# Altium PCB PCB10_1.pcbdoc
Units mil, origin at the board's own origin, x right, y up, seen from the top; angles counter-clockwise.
Board outline 2455 x 1010 mil, 6 copper layers (Top Layer, GND, Inner2, Inner3, 3.3, Bottom Layer); 64 components, 81 nets, 315 pads, 60 vias.
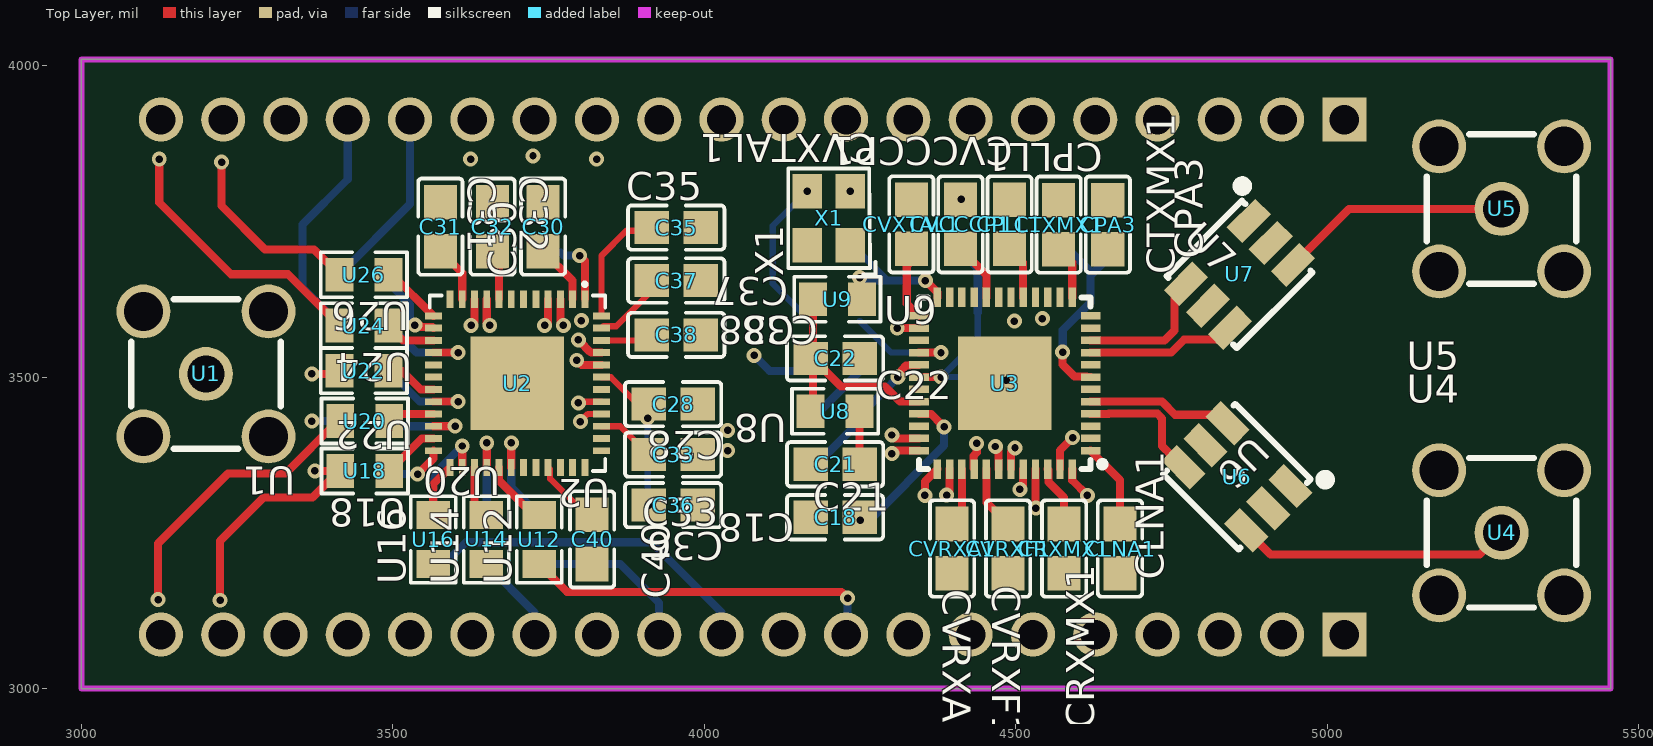
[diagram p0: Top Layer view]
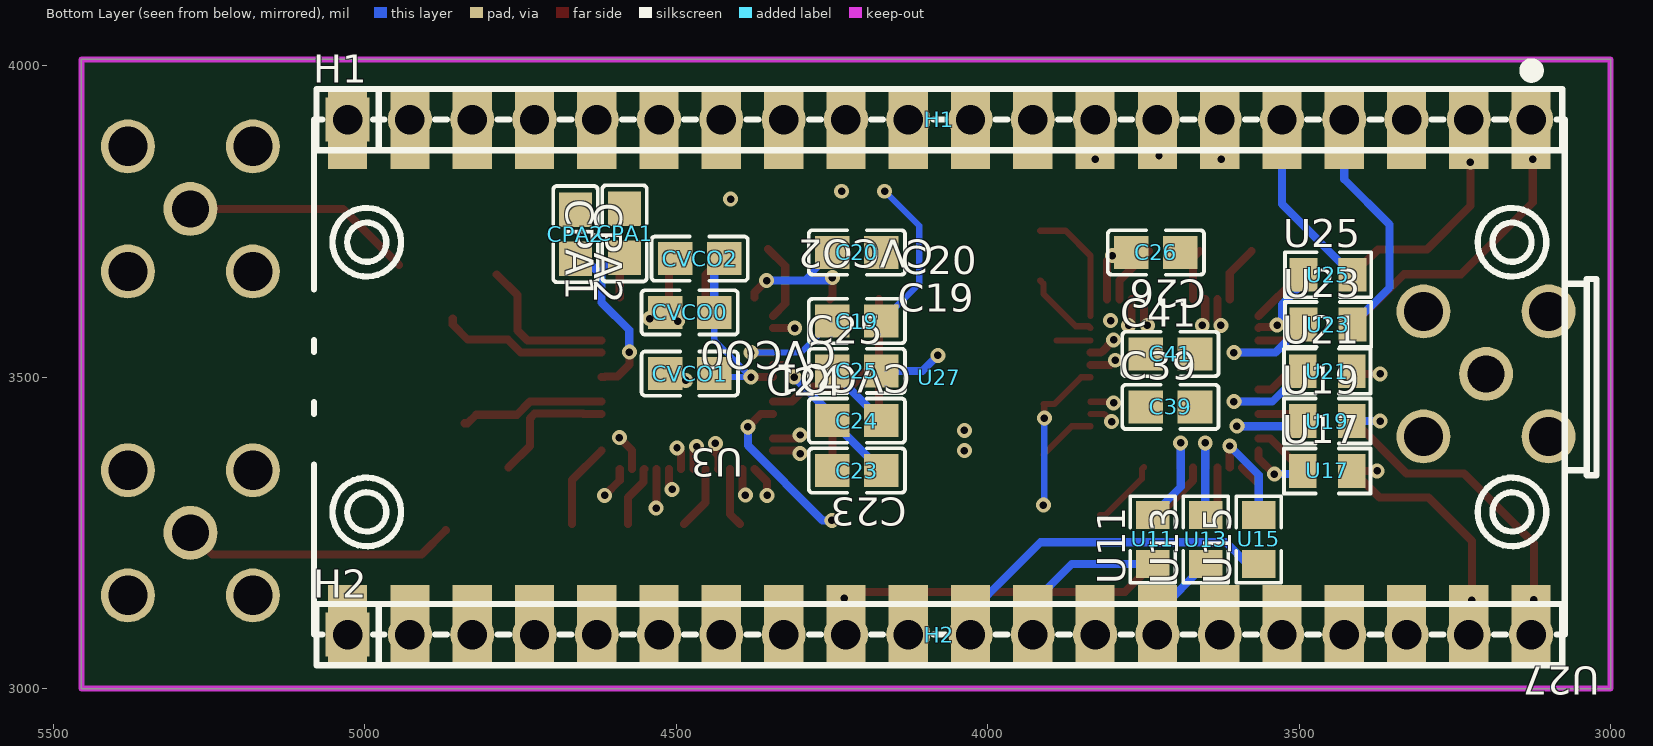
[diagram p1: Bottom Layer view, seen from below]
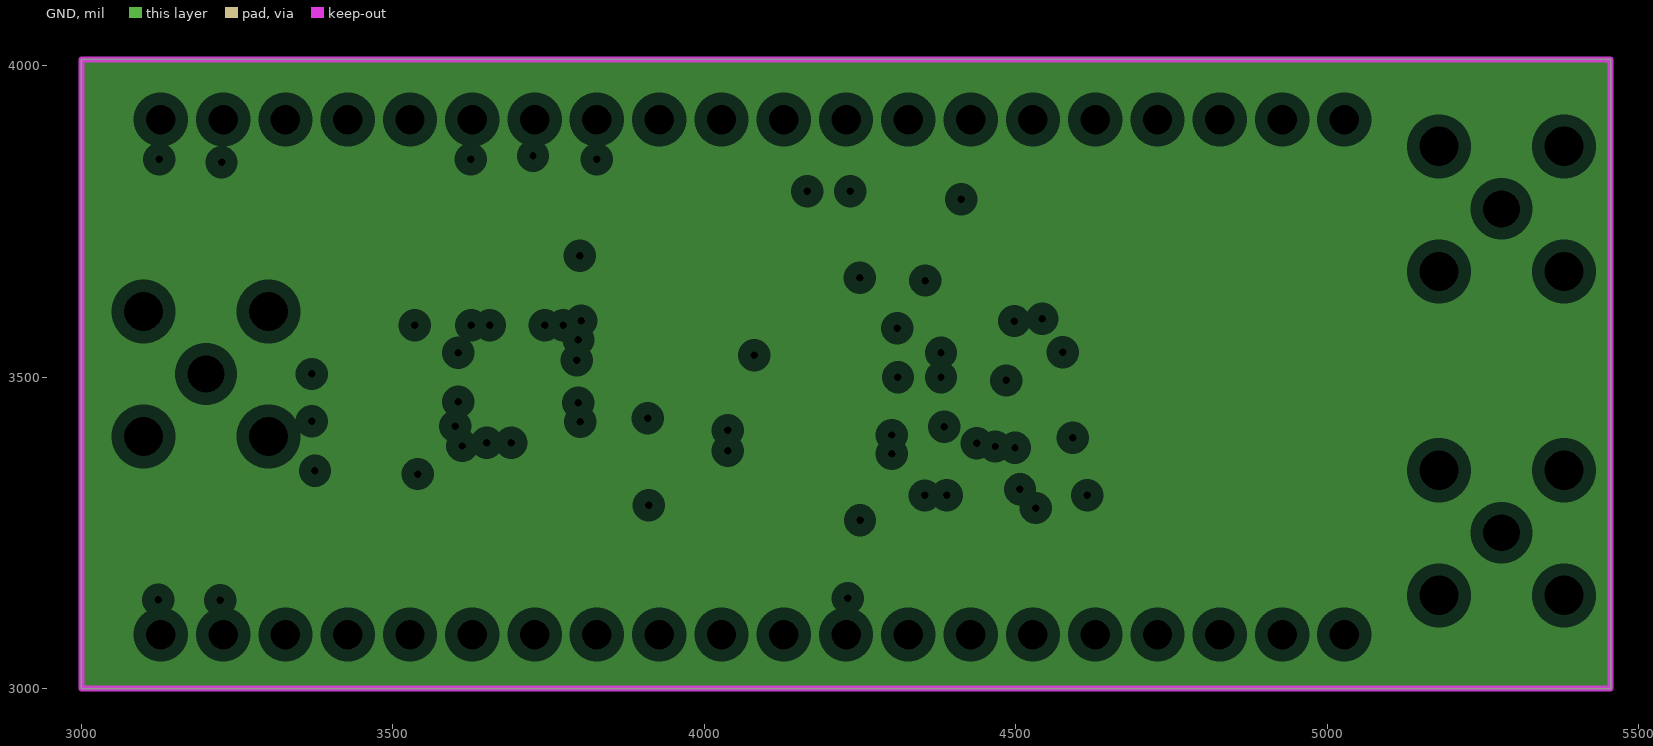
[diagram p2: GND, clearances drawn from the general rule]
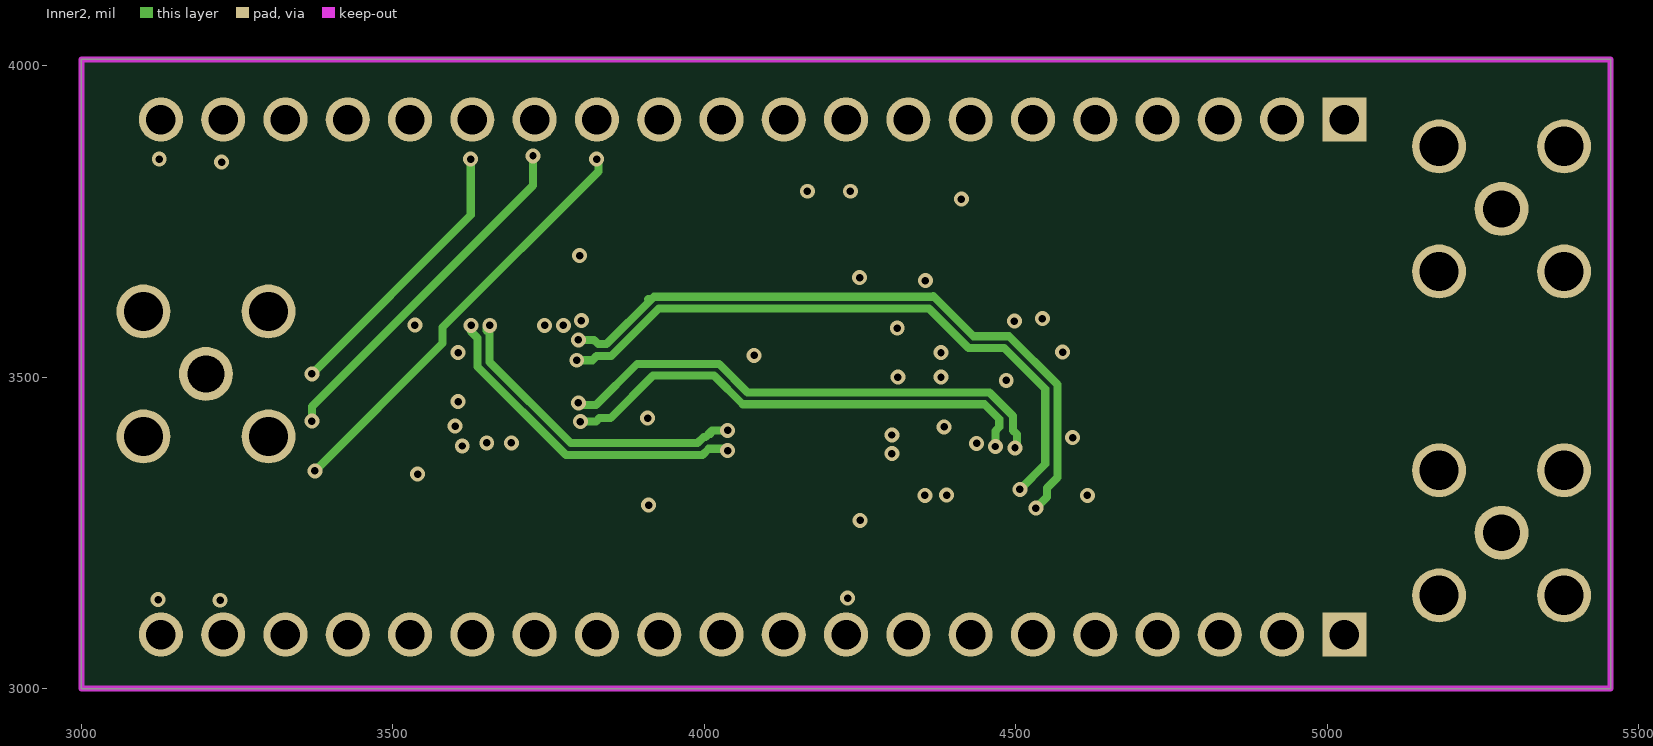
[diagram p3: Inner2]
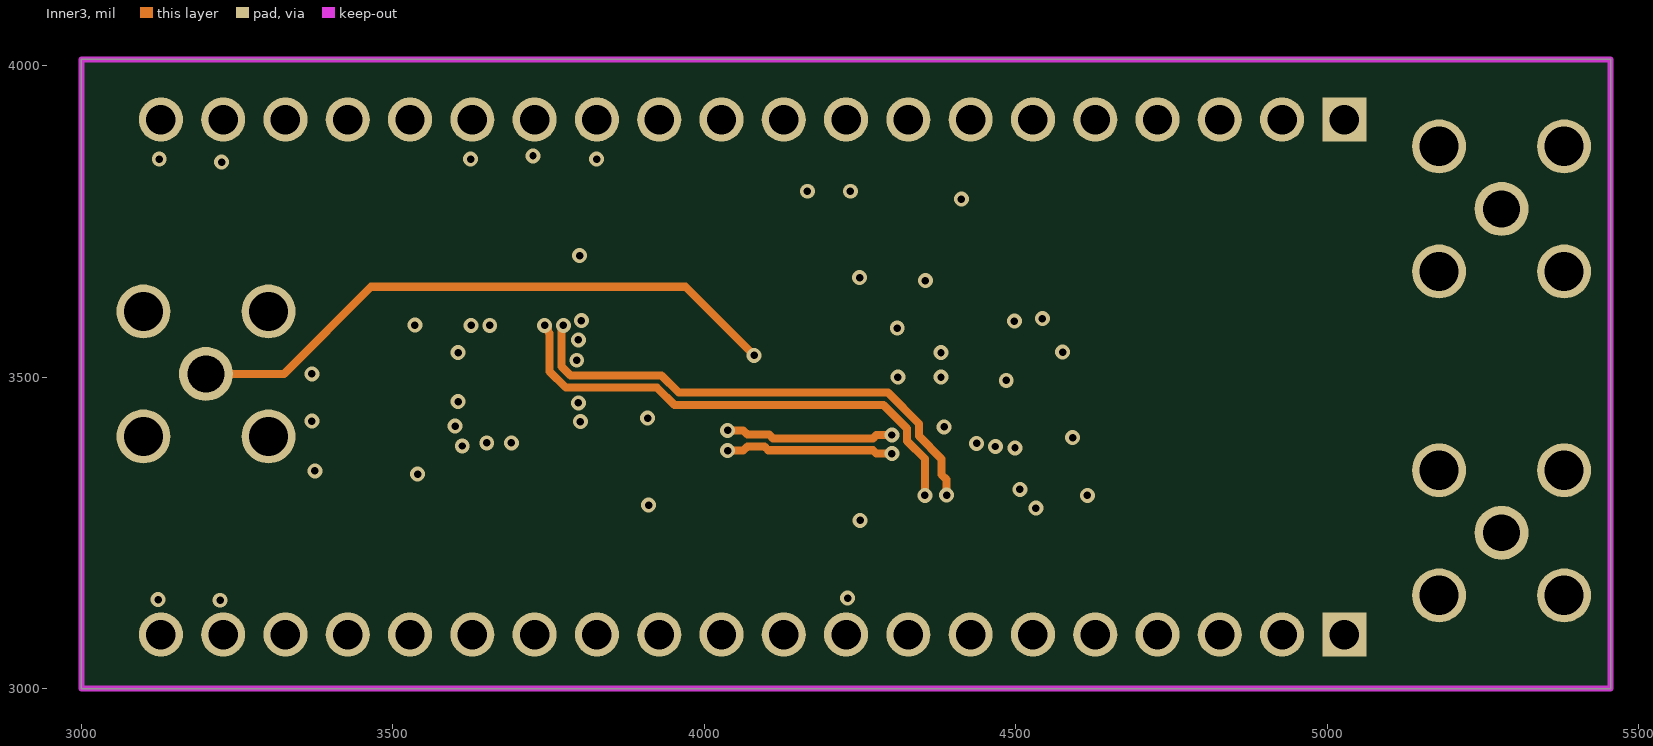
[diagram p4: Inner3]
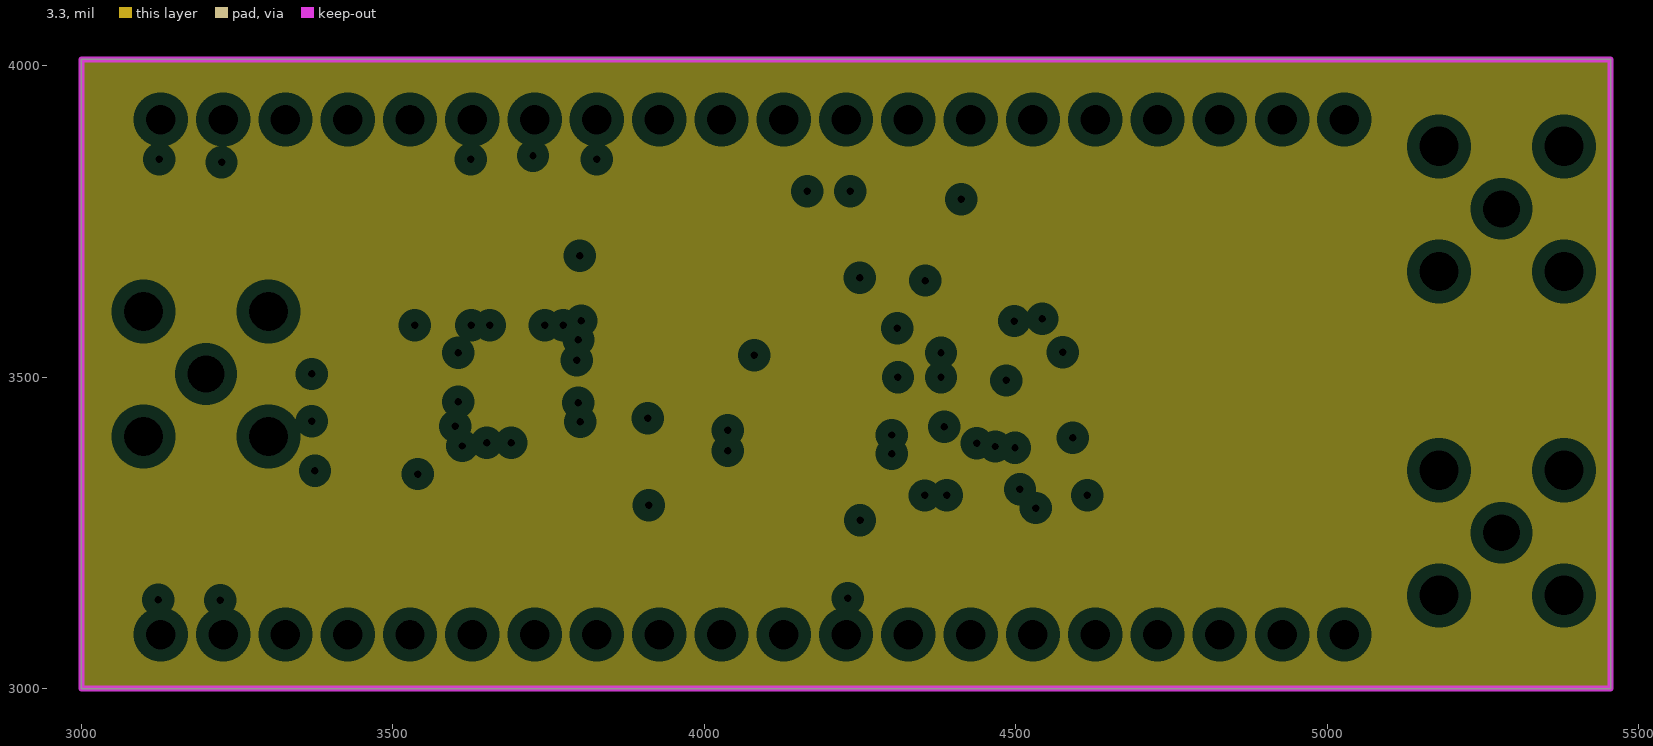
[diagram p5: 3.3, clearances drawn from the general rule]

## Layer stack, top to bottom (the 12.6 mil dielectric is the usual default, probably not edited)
Top Layer: signal copper (thickness not stored)
Dielectric: dielectric 12.6, FR-4, Dk 4.8
GND: plane copper (thickness not stored)
Dielectric: dielectric 12.6, FR-4, Dk 4.8
Inner2: signal copper (thickness not stored)
Dielectric: dielectric 12.6, FR-4, Dk 4.8
Inner3: signal copper (thickness not stored)
Dielectric: dielectric 12.6, FR-4, Dk 4.8
3.3: plane copper (thickness not stored)
Dielectric: dielectric 12.6, FR-4, Dk 4.8
Bottom Layer: signal copper (thickness not stored)

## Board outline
3000,4010 5455,4010 5455,3000 3000,3000

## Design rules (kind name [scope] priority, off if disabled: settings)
BoardOutlineClearance copperThickness1oz [All] p0: genericclearance=10 ignorepadtopadclearanceinfootprint=FALSE except(0: Arc-SplitContinuation Track-SplitContinuation SMDPad-SplitContinuation THPad-SplitContinuation Via-SplitContinuation Fill-SplitContinuation Poly-SplitContinuation Region-SplitContinuation Text-SplitContinuation; 6: Track-CutoutEdge SMDPad-CutoutEdge THPad-CutoutEdge Via-CutoutEdge Region-CutoutEdge; 11.8: Track-OutlineEdge SMDPad-OutlineEdge THPad-OutlineEdge Via-OutlineEdge Fill-OutlineEdge Region-OutlineEdge Poly-OutlineEdge Text-OutlineEdge Fill-CutoutEdge)
BoardOutlineClearance copperThickness2oz [All] p0: genericclearance=10 ignorepadtopadclearanceinfootprint=FALSE except(0: Arc-SplitContinuation Track-SplitContinuation SMDPad-SplitContinuation THPad-SplitContinuation Via-SplitContinuation Fill-SplitContinuation Poly-SplitContinuation Region-SplitContinuation Text-SplitContinuation; 6: Track-CutoutEdge SMDPad-CutoutEdge THPad-CutoutEdge Via-CutoutEdge Region-CutoutEdge; 11.8: Track-OutlineEdge SMDPad-OutlineEdge THPad-OutlineEdge Via-OutlineEdge Fill-OutlineEdge Region-OutlineEdge Poly-OutlineEdge Text-OutlineEdge Fill-CutoutEdge)
Clearance copperThickness1oz [(InNet('$1I297\BYPASS') OR InNet('GND') OR InNet('$1I297\XTAL') OR InNet('$1I297\$1N2490') OR InNet('$1I297\CPOUT') OR InNet('$1I297\$1N1515') OR InNet('$1I297\TUNE') OR InNet('$1I297\$1N2254') OR InNet('3.3') OR InNet('$1I297\D6') OR InNet('$1I297\RXP') OR InNet('$1I297\RXN') OR InNet('$1I297\D7') OR InNet('$1I297\D3') OR InNet('$1I297\TXP') OR InNet('$1I297\TXN') OR InNet('$1I297\D2') OR InNet('$1I297\SHDN#') OR InNet('$1I297\D4') OR InNet('$1I297\D5') OR InNet('$1I297\CS#') OR InNet('$1I297\RSSI') OR InNet('$1I297\SCLK') OR InNet('$1I297\DIN') OR InNet('$1I297\CLKBUF') OR InNet('$1I297\PLL_LOCK') OR InNet('$1I297\D1') OR InNet('$1I297\RXHP') OR InNet('$1I297\RXTX_MODE') OR InNet('$1I297\$1N1513') OR InNet('$1I297\$1N1514') OR InNet('$1I61\$1N1654') OR InNet('$1I61\$1N1653') OR InNet('$1I61\$1N1602') OR InNet('$1I61\BBC_CLK') OR InNet('$1I61\$1N1651') OR InNet('$1I61\$1N1648') OR InNet('$1I61\$1N1645') OR InNet('$1I61\$1N1642') OR InNet('$1I61\$1N1639') OR InNet('$1I61\$1N1636') OR InNet('$1I61\$1N1633') OR InNet('$1I61\$1N1662') OR InNet('$1I61\$1N1628') OR InNet('$1I61\$1N1625') OR InNet('$1I61\$1N1620') OR InNet('$1I61\$1N1617') OR InNet('$1I61\$1N1614') OR InNet('$1I61\$1N1611') OR InNet('$1I61\$1N1608') OR InNet('$1I61\$1N1605') OR InNet('$1I61\DIN') OR InNet('$1I61\SCLK') OR InNet('$1I61\CS#') OR InNet('$1I61\BBC_DD7') OR InNet('$1I61\BBC_DD6') OR InNet('$1I61\BBC_DD5') OR InNet('$1I61\BBC_DD4') OR InNet('$1I61\BBC_DD3') OR InNet('$1I61\BBC_DD2') OR InNet('$1I61\BBC_DD1') OR InNet('$1I61\BBC_DD0') OR InNet('$1I61\BBC_DA7') OR InNet('$1I61\BBC_DA6') OR InNet('$1I61\BBC_DA5') OR InNet('$1I61\BBC_DA4') OR InNet('$1I61\BBC_DA3') OR InNet('$1I61\BBC_DA2') OR InNet('$1I61\BBC_DA1') OR InNet('$1I61\BBC_DA0') OR InNet('RXQN') OR InNet('RXQP') OR InNet('RXIN') OR InNet('RXIP') OR InNet('TXQN') OR InNet('TXQP') OR InNet('TXIN') OR InNet('TXIP') OR InNet('+5V') OR InNet('VCC') OR InNet('$1I297\$1N3884'))] p1: gap=7 ignorepadtopadclearanceinfootprint=FALSE except(4: Track-Track; 6: Track-SMDPad SMDPad-SMDPad Track-THPad SMDPad-THPad THPad-THPad Track-Via SMDPad-Via THPad-Via Via-Via SMDPad-Fill THPad-Fill Via-Fill Fill-Fill Track-Region SMDPad-Region THPad-Region Via-Region Region-Region Track-Poly SMDPad-Poly THPad-Poly Via-Poly Fill-Poly Region-Poly Poly-Poly Track-Text SMDPad-Text THPad-Text Via-Text Fill-Text Region-Text Poly-Text Text-Text; 6.9: Track-Hole SMDPad-Hole THPad-Hole Via-Hole Fill-Hole Region-Hole Poly-Hole Text-Hole Sheet-Hole; 11.8: Track-Fill Fill-Region Track-Sheet SMDPad-Sheet THPad-Sheet Via-Sheet Fill-Sheet Region-Sheet Poly-Sheet Text-Sheet)
Clearance copperThickness2oz [All] p1: gap=7 ignorepadtopadclearanceinfootprint=FALSE except(6: Track-SMDPad SMDPad-SMDPad Track-THPad SMDPad-THPad THPad-THPad Track-Via SMDPad-Via THPad-Via Via-Via SMDPad-Fill THPad-Fill Via-Fill Fill-Fill Track-Region SMDPad-Region THPad-Region Via-Region Region-Region Track-Poly SMDPad-Poly THPad-Poly Via-Poly Fill-Poly Region-Poly Poly-Poly Track-Text SMDPad-Text THPad-Text Via-Text Fill-Text Region-Text Poly-Text Text-Text; 6.9: Track-Hole SMDPad-Hole THPad-Hole Via-Hole Fill-Hole Region-Hole Poly-Hole Text-Hole Sheet-Hole; 8: Track-Track; 11.8: Track-Fill Fill-Region Track-Sheet SMDPad-Sheet THPad-Sheet Via-Sheet Fill-Sheet Region-Sheet Poly-Sheet Text-Sheet)
DiffPairsRouting differentialPair [All] p1: maxuncoupledlength=10 minlimit=6 maxlimit=6 mostfreqgap=6 toplayer_minwidth=5 toplayer_prefwidth=10 toplayer_maxwidth=100 bottomlayer_minwidth=5 bottomlayer_prefwidth=10 bottomlayer_maxwidth=100 midlayer2_minwidth=5 midlayer2_prefwidth=10 midlayer2_maxwidth=100 midlayer3_minwidth=5 midlayer3_prefwidth=10 midlayer3_maxwidth=100
PasteMaskExpansion pasteMaskExpansion [All] p1: expansion=0
PlaneConnect innerPlane [All] p1: planeconnectstyle=Relief reliefexpansion=20 reliefentries=4 reliefconductorwidth=10 reliefairgap=10
PolygonConnect copperRegion [All] p1: connectstyle=Relief reliefentries=4 reliefconductorwidth=10 polygonreliefangle="90 Angle" airgapwidth=10
RoutingVias viaSize [All] p1: viastyle="Through Hole" holewidth=12.0078 minholewidth=11.811 maxholewidth=248.0314 width=24.0158 minwidth=19.685 maxwidth=393.7008
SolderMaskExpansion solderMaskExpansion [All] p1: useseparateexpansions=TRUE expansion=2 expansionbottom=2
Width copperThickness1oz [All] p1: maxlimit=100 minlimit=5 preferedwidth=10
Width copperThickness2oz [All] p1: maxlimit=100 minlimit=8 preferedwidth=10

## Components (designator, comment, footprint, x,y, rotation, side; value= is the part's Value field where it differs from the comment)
C18 "CAP_0603" C0805 4210,3275 r0 top
C19 "CAP_0603" C0805 4210,3590 r0 bottom
C20 "CAP_0603" C0805 4210,3700 r0 bottom
C21 "CAP_0603" C0805 4210,3360 r0 top
C22 "CAP_0603" C0805 4210,3530 r180 top
C23 "CAP_0603" C0805 4210,3350 r0 bottom
C24 "CAP_0805" C0805 4210,3430 r180 bottom
C25 "CAP_0805" C0805 4210,3510 r180 bottom
C26 "CAP_0805" C0805 3730,3700 r0 bottom
C28 "CAP_0805" C0805 3950,3456.6 r180 top
C30 "CAP_0805" C0805 3741.35,3741.45 r90 top
C31 "CAP_0805" C0805 3576.3,3741.45 r270 top
C32 "CAP_0805" C0805 3659.94,3741.45 r270 top
C33 "CAP_0805" C0805 3950,3375.47 r0 top
C35 "CAP_0805" C0805 3955,3740 r0 top
C36 "CAP_0805" C0805 3950,3294.34 r180 top
C37 "CAP_0805" C0805 3955,3655 r180 top
C38 "CAP_0805" C0805 3955,3567.73 r180 top
C39 "CAP_0805" C0805 3706.63,3452.1 r180 bottom
C40 "CAP_0805" C0805 3819.94,3239.34 r90 top
C41 "CAP_0805" C0805 3706.63,3537.1 r180 bottom
CLNA1 "CAP_0603" C0805 4667.43,3224.74 r270 top
CPA1 "CAP_0603" C0805 4583.06,3730.72 r90 bottom
CPA2 "CAP_0603" C0805 4661.8,3729.46 r90 bottom
CPA3 "CAP_0603" C0805 4647.79,3744.74 r90 top
CPLL1 "CAP_0603" C0805 4490.11,3745.09 r90 top
CRXMX1 "CAP_0603" C0805 4577.55,3224.74 r270 top
CTXMX1 "CAP_0603" C0805 4568.95,3744.74 r90 top
CVCCCP1 "CAP_0603" C0805 4411.27,3745.09 r90 top
CVCO0 "CAP_0603" C0805 4478.42,3603.74 r0 bottom
CVCO1 "CAP_0603" C0805 4478.37,3505.55 r0 bottom
CVCO2 "CAP_0603" C0805 4462.43,3690.09 r0 bottom
CVRXA1 "CAP_0603" C0805 4397.79,3224.74 r270 top
CVRXF1 "CAP_0603" C0805 4487.67,3224.74 r270 top
CVXTAL1 "CAP_0603" C0805 4332.43,3745.09 r90 top
H1 "HDR-M_2.54_1x20P" HDR-TH_20P-P2.54-V-M-1 4077.6,3913.39 r180 bottom
H2 "HDR-M_2.54_1x20P" HDR-TH_20P-P2.54-V-M-1 4077.6,3086.61 r180 bottom
U1 "MCX5.08-H5_C9900009324" SMA-TH_MCX5.08-H5 3200,3505 r180 top
U2 "MAX5864ETM+" QFN-48_L7.0-W7.0-P0.50-BL-EP5.1 3700,3490 r180 top
U3 "MAX2831ETM+T" TQFN-48_L7.0-W7.0-P0.50-TL-EP5.6 4482.43,3490.09 r180 top
U4 "MCX5.08-H5_C9900009324" SMA-TH_MCX5.08-H5 5280,3250 r0 top
U5 "MCX5.08-H5_C9900009324" SMA-TH_MCX5.08-H5 5280,3770 r0 top
U6 "TCM2-43X+" IND-SMD_6P-L4.1-W3.8-P1.27-TL 4855,3340 r225 top
U7 "TCM2-43X+" IND-SMD_6P-L4.1-W3.8-P1.27-TL 4859.01,3665 r315 top
U8 "SCR0805J1M" R0805 4210,3445 r0 top
U9 "SCR0805J1M" R0805 4213.74,3625 r0 top
U11 "3R00" R0805 3734.94,3239.34 r90 bottom
U12 "3R00" R0805 3734.94,3239.34 r90 top
U13 "3R00" R0805 3649.94,3239.34 r90 bottom
U14 "3R00" R0805 3649.94,3239.34 r90 top
U15 "3R00" R0805 3564.94,3239.34 r90 bottom
U16 "3R00" R0805 3564.94,3239.34 r90 top
U17 "3R00" R0805 3454.94,3349.34 r180 bottom
U18 "3R00" R0805 3454.94,3349.34 r180 top
U19 "3R00" R0805 3454.94,3429.34 r180 bottom
U20 "3R00" R0805 3454.94,3429.34 r180 top
U21 "3R00" R0805 3454.94,3509.34 r180 bottom
U22 "3R00" R0805 3453.53,3510 r180 top
U23 "3R00" R0805 3453.53,3584.34 r180 bottom
U24 "3R00" R0805 3453.53,3582.61 r180 top
U25 "3R00" R0805 3453.53,3664.34 r180 bottom
U26 "3R00" R0805 3453.53,3664.34 r180 top
U27 "PICO" comm-smd_l51.0-w21.0-p2.54_sc0916 4090,3500 r0 bottom
X1 "SX3M40.000E20F30THN" OSC-SMD_4P-L3.2-W2.5-BL 4200,3755 r90 top

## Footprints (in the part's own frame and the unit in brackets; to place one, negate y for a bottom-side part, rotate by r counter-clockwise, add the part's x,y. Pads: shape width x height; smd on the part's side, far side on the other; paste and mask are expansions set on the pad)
C0805 [mm]
  rect 1.41x1.35 smd: 1(-1,0) 2(1,0)
  silkscreen extent -1.96,-0.9 1.96,0.9
comm-smd_l51.0-w21.0-p2.54_sc0916 [mm]
  rect 1.6x3.2 smd: 1(-24.445,-10.087) 2(-21.905,-10.087) 3(-19.365,-10.087) 4(-16.825,-10.087) 5(-14.285,-10.087) 6(-11.745,-10.087) 7(-9.205,-10.087) 8(-6.665,-10.087) 9(-4.125,-10.087) 10(-1.585,-10.087) 11(0.955,-10.087) 12(3.495,-10.087) 13(6.035,-10.087) 14(8.575,-10.087) 15(11.115,-10.087) 16(13.655,-10.087) 17(16.195,-10.087) 18(18.735,-10.087) 19(21.275,-10.087) 20(23.815,-10.087) 21(23.815,10.087) 22(21.275,10.087) 23(18.735,10.087) 24(16.195,10.087) 25(13.655,10.087) 26(11.115,10.087) 27(8.575,10.087) 28(6.035,10.087) 29(3.495,10.087) 30(0.955,10.087) 31(-1.585,10.087) 32(-4.125,10.087) 33(-6.665,10.087) 34(-9.205,10.087) 35(-11.745,10.087) 36(-14.285,10.087) 37(-16.825,10.087) 38(-19.365,10.087) 39(-21.905,10.087) 40(-24.445,10.087)
  silkscreen extent -27.11,-12.75 25.18,10.5
HDR-TH_20P-P2.54-V-M-1 [mm]
  rect 1.8x1.8 hole 1.2: 1(-24.13,0)
  round 1.8 hole 1.2: 2(-21.59,0) 3(-19.05,0) 4(-16.51,0) 5(-13.97,0) 6(-11.43,0) 7(-8.89,0) 8(-6.35,0) 9(-3.81,0) 10(-1.27,0) 11(1.27,0) 12(3.81,0) 13(6.35,0) 14(8.89,0) 15(11.43,0) 16(13.97,0) 17(16.51,0) 18(19.05,0) 19(21.59,0) 20(24.13,0)
  silkscreen extent -25.4,-1.25 25.4,1.25
IND-SMD_6P-L4.1-W3.8-P1.27-TL [mm]
  rect 0.9x1.657 smd: 1(-1.27,1.814) 2(0,1.814) 3(1.27,1.814) 4(1.27,-1.814) 5(0,-1.814) 6(-1.27,-1.814)
  silkscreen extent -2.66,-2.2 2.05,2.83
OSC-SMD_4P-L3.2-W2.5-BL [mm]
  rect 1.4x1.2 smd: 1(-1.1,-0.875) 2(1.1,-0.875) 3(1.1,0.875) 4(-1.1,0.875)
  silkscreen extent -2.29,-1.9 2.03,1.65
QFN-48_L7.0-W7.0-P0.50-BL-EP5.1 [mm]
  rect 0.28x0.7 smd: 1(-2.75,-3.427) 2(-2.25,-3.427) 3(-1.75,-3.427) 4(-1.25,-3.427) 5(-0.75,-3.427) 6(-0.25,-3.427) 7(0.25,-3.427) 8(0.75,-3.427) 9(1.25,-3.427) 10(1.75,-3.427) 11(2.25,-3.427) 12(2.75,-3.427) 25(2.75,3.427) 26(2.25,3.427) 27(1.75,3.427) 28(1.25,3.427) 29(0.75,3.427) 30(0.25,3.427) 31(-0.25,3.427) 32(-0.75,3.427) 33(-1.25,3.427) 34(-1.75,3.427) 35(-2.25,3.427) 36(-2.75,3.427)
  rect 0.7x0.28 smd: 13(3.427,-2.75) 14(3.427,-2.25) 15(3.427,-1.75) 16(3.427,-1.25) 17(3.427,-0.75) 18(3.427,-0.25) 19(3.427,0.25) 20(3.427,0.75) 21(3.427,1.25) 22(3.427,1.75) 23(3.427,2.25) 24(3.427,2.75) 37(-3.427,2.75) 38(-3.427,2.25) 39(-3.427,1.75) 40(-3.427,1.25) 41(-3.427,0.75) 42(-3.427,0.25) 43(-3.427,-0.25) 44(-3.427,-0.75) 45(-3.427,-1.25) 46(-3.427,-1.75) 47(-3.427,-2.25) 48(-3.427,-2.75)
  rect 3.81x3.81 smd: 49(0,0)
  silkscreen extent -3.58,-4.11 3.58,3.58
R0805 [mm]
  rect 1.133x1.377 smd: 1(-1,0) 2(1,0)
  silkscreen extent -1.76,-0.92 1.76,0.92
SMA-TH_MCX5.08-H5 [mm]
  round 2.2 hole 1.6: 1(-2.55,-2.55) 2(-2.55,2.55) 3(2.55,2.55)
  round 2.2 hole 1.6 copper offset 0,0: 4(2.55,-2.55)
  round 2.2 hole 1.5: 5(0,0)
  silkscreen extent -3.05,-3.05 3.05,3.05
TQFN-48_L7.0-W7.0-P0.50-TL-EP5.6 [mm]
  rect 0.8x0.3 smd: 1(-3.5,2.751) 2(-3.5,2.25) 3(-3.5,1.75) 4(-3.5,1.251) 5(-3.5,0.75) 6(-3.5,0.251) 7(-3.5,-0.249) 8(-3.5,-0.749) 9(-3.5,-1.25) 10(-3.5,-1.75) 11(-3.5,-2.249) 12(-3.5,-2.748) 25(3.5,-2.748) 26(3.5,-2.249) 27(3.5,-1.75) 28(3.5,-1.25) 29(3.5,-0.749) 30(3.5,-0.249) 31(3.5,0.251) 32(3.5,0.75) 33(3.5,1.251) 34(3.5,1.75) 35(3.5,2.25) 36(3.5,2.751)
  rect 0.3x0.8 smd: 13(-2.751,-3.5) 14(-2.251,-3.5) 15(-1.75,-3.5) 16(-1.25,-3.5) 17(-0.749,-3.5) 18(-0.25,-3.5) 19(0.249,-3.5) 20(0.749,-3.5) 21(1.25,-3.5) 22(1.75,-3.5) 23(2.251,-3.5) 24(2.751,-3.5) 37(2.751,3.5) 38(2.251,3.5) 39(1.75,3.5) 40(1.25,3.5) 41(0.749,3.5) 42(0.25,3.5) 43(-0.25,3.5) 44(-0.749,3.5) 45(-1.25,3.5) 46(-1.75,3.5) 47(-2.251,3.5) 48(-2.751,3.5)
  rect 3.81x3.81 smd: 49(0,0.001)
  silkscreen extent -4.11,-3.5 3.5,3.5

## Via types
v1: diameter 24.02, hole 12.01, Top Layer to Bottom Layer, 42 vias
v2: diameter 24, hole 12, Top Layer to Bottom Layer, 18 vias

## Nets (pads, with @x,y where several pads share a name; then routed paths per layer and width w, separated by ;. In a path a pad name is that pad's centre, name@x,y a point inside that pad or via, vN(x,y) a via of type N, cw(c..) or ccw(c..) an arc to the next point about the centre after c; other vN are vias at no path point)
3.3: CLNA1.1 CPA1.1 CPA2.1 CPA3.1 CPLL1.1 CRXMX1.1 CTXMX1.1 CVCCCP1.1 CVCO0.1 CVCO1.1 CVCO2.1 CVRXA1.1 CVRXF1.1 CVXTAL1.1 U3.1 U3.7 U3.13 U3.17 U3.20 U3.25 U3.27 U3.30 U3.39 U3.41 U3.46 | length 1479.4
  Top Layer w13: U3.30 v2(4380,3499.9) ; U3.25 4325,3617.94 4325,3678.29 CVXTAL1.1@4352.43,3705.72 ; CVRXA1.1 4413.54,3279.86 U3.39 ; CVCCCP1.1 4452.93,3664.07 U3.20 ; U3.41 4452.93,3298.85 CVRXF1.1 ; CPLL1.1 4511.94,3683.9 U3.17 ; U3.46 4552.65,3350.98 4552.65,3331.38 4577.55,3306.48 CRXMX1.1 ; CTXMX1.1 4590.73,3683.59 U3.13 ; v2(4575.41,3539.9) 4575.23,3539.72 4575.23,3520.29 4594.31,3501.21 4613.92,3501.21 4615.23,3499.9 U3.7 ; U3.1 4667.43,3334.59 CLNA1.1
  Bottom Layer w10: CVCO1.1 4433.35,3499.9 v2(4380,3499.9) 4439.05,3558.95 CVCO0.1
  Bottom Layer w13: CVCO2.1 4439.05,3674.11 CVCO0.1 ; v2(4575.41,3539.9) 4575.41,3575.41 4620,3620 4620,3663.29 ; CPA1.1@4583.06,3706.35 4620,3669.42 4620,3663.29 ; CPA2.1@4661.8,3705.09 4620,3663.29
  other v1: 3802.68,3590.72
$1I61\$1N1602: C37.2 U2.47 | length 121.8
  Top Layer w10: U2.47 3838.13,3581.77 3858.54,3581.77 3910.63,3633.87 3910.63,3650 C37.2
$1I61\$1N1605: U2.30 U11.2 | length 173.5
  Top Layer w13: U2.30 v1(3690.16,3394.34)
  Bottom Layer w13: v1(3690.16,3394.34) 3690.16,3323.48 U11.2
$1I61\$1N1608: U2.29 U12.2 | length 108.5
  Top Layer w13: U2.29 3670.47,3333.8 3725.57,3278.71 U12.2
$1I61\$1N1611: U2.28 U13.2 | length 155.3
  Top Layer w13: U2.28 v1(3650.79,3394.34)
  Bottom Layer w13: U13.2 3650.79,3279.56 v1(3650.79,3394.34)
$1I61\$1N1614: U2.27 U14.2 | length 84.2
  Top Layer w13: U2.27 3631.1,3297.54 U14.2
$1I61\$1N1617: U2.26 U15.2 | length 164.2
  Top Layer w13: U2.26 v1(3611.42,3389.34)
  Bottom Layer w13: U15.2 3564.94,3342.85 v1(3611.42,3389.34)
$1I61\$1N1620: U2.25 U16.2 | length 87.5
  Top Layer w13: U16.2 3564.94,3328.27 U2.25
$1I61\$1N1625: U2.24 U17.1 | length 95.5
  Top Layer w13: v1(3539.94,3344.34) 3565.06,3369.46 U2.24
  Bottom Layer w13: U17.1 3499.31,3344.34 v1(3539.94,3344.34)
$1I61\$1N1628: U2.23 U18.1 | length 92.3
  Top Layer w13: U18.1 3546.39,3401.42 U2.23
$1I61\$1N1633: U2.21 U20.1 | length 75.5
  Top Layer w13: U20.1 3505.76,3440.79 U2.21
$1I61\$1N1636: U2.20 U21.1 | length 170.7
  Top Layer w13: U2.20 v1(3604.94,3460.47)
  Bottom Layer w13: U21.1 3543.17,3460.47 v1(3604.94,3460.47)
$1I61\$1N1639: U2.19 U22.1 | length 84.5
  Top Layer w13: U22.1 3514.94,3510 3544.78,3480.16 U2.19
$1I61\$1N1642: U2.16 U23.1 | length 170.6
  Top Layer w13: U2.16 v1(3604.94,3539.21)
  Bottom Layer w13: U23.1 3538.03,3539.21 v1(3604.94,3539.21)
$1I61\$1N1645: U2.15 U24.1 | length 82
  Top Layer w13: U24.1 3516.62,3558.9 U2.15
$1I61\$1N1648: U2.14 U25.1 | length 130.3
  Top Layer w13: v1(3535.23,3583.36) 3543.02,3583.36 3546.11,3580.27 3563.37,3580.27 U2.14
  Bottom Layer w13: U25.1 3492.9,3651.39 3527.68,3616.61 3527.68,3590.91 v1(3535.23,3583.36)
$1I61\$1N1651: U2.13 U26.1 | length 99.5
  Top Layer w13: U26.1 3498.99,3664.34 U2.13
$1I61\$1N1653: C35.1 U2.48 | length 194
  Top Layer w10: U2.48 3834.94,3694.94 3875,3735 C35.1@3915.63,3735
$1I61\$1N1654: C26.2 U2.1 | length 106.2
  Top Layer w13: v1(3800,3695) 3808.27,3686.73 U2.1
  Bottom Layer w13: C26.2 3774.37,3695 v1(3800,3695)
$1I61\$1N1662: U2.22 U19.1 | length 143.9
  Top Layer w13: U2.22 v1(3599.94,3421.1)
  Bottom Layer w13: U19.1 3502.54,3421.1 v1(3599.94,3421.1)
$1I61\BBC_CLK: U2.6
$1I61\BBC_DA0: U26.2 U27.2 | length 305
  Top Layer w13: v1(3225,3845) 3225,3775 3295,3705 3373.5,3705 U26.2
$1I61\BBC_DA1: U25.2 U27.5 | length 279.8
  Bottom Layer w13: U25.2 3527.59,3777.77 U27.5
$1I61\BBC_DA2: U24.2 U27.1 | length 440.9
  Top Layer w13: v1(3125,3850) 3125,3780 3240,3665 3331.78,3665 U24.2
$1I61\BBC_DA3: U23.2 U27.4 | length 367.4
  Bottom Layer w13: U23.2 3355,3643.5 3355,3745 3427.59,3817.59 U27.4
$1I61\BBC_DA4: U22.2 U27.6 | length 496.9
  Top Layer w13: v1(3370,3505) 3409.16,3505 U22.2
  Inner2 w13: v1(3370,3505) 3625,3760 v1(3625,3850)
$1I61\BBC_DA5: U21.2
$1I61\BBC_DA6: U20.2 U27.40 | length 460.9
  Top Layer w13: v1(3123.22,3142.61) 3123.22,3232.61 3235.61,3345 3327.39,3345 U20.2@3412.39,3430
$1I61\BBC_DA7: U19.2 U27.7 | length 618.3
  Inner2 w13: v1(3370,3429.34) 3370,3452.76 3725,3807.76 v1(3725,3855)
  Bottom Layer w13: v1(3370,3429.34) U19.2
$1I61\BBC_DD0: U18.2 U27.8 U27.39 | length 1054.7
  Top Layer w13: v1(3222.62,3141.72) 3222.62,3236.72 3292.62,3306.72 3371.12,3306.72 U18.2@3411.78,3347.38 ; v1(3375,3349.34) U18.2
  Inner2 w13: v1(3375,3349.34) 3580,3554.34 3580,3580 3830,3830 v1@3830,3845
  other v1: 3827.08,3850
$1I61\BBC_DD1: U17.2
$1I61\BBC_DD2: U16.1
$1I61\BBC_DD3: U15.1 U27.31 | length 543.1
  Bottom Layer w13: U15.1 3582.88,3199.97 3617.66,3234.75 3915.25,3234.75 4027.59,3122.41 U27.31
$1I61\BBC_DD4: U14.1
$1I61\BBC_DD5: U13.1 U27.34 | length 129.3
  Bottom Layer w13: U13.1 3727.59,3122.31 U27.34
$1I61\BBC_DD6: U12.1 U27.29 | length 561
  Top Layer w13: U12.1 3779.9,3155 4220,3155 v1(4230,3145)
  Bottom Layer w13: U27.29 4230,3105.27 v1(4230,3145)
$1I61\BBC_DD7: U11.1 U27.32 | length 253.1
  Bottom Layer w13: U11.1 3865.03,3199.97 3927.59,3137.41 U27.32
$1I61\CS#: U2.36
$1I61\DIN: U2.34
$1I61\SCLK: U2.35
$1I297\$1N1513: U4.5 U6.3 | length 440.6
  Top Layer w13: U6.3 4909.29,3215 5244.99,3215 U4.5
$1I297\$1N1514: U5.5 U7.3 | length 372.4
  Top Layer w13: U7.3 5034.73,3770.01 U5.5
$1I297\$1N1515: C21.2 U8.2 | length 85
  Top Layer w13: C21.2 U8.2
$1I297\$1N2254: C23.1 C24.1 U3.29 | length 253.2
  Top Layer w13: v1(4310.9,3500) 4316.41,3505.51 4316.41,3510.98 4323.72,3518.29 4329.19,3518.29 4330.5,3519.6 U3.29
  Bottom Layer w13: C23.1 4249.37,3428.74 C24.1 4249.37,3438.01 4289.61,3478.25 4289.61,3478.71 v1(4310.9,3500)
$1I297\$1N2490: C19.1 X1.3 | length 256.8
  Bottom Layer w10: v1(4165.55,3798.31) 4110,3742.76 4110,3650 4170,3590 C19.1
$1I297\$1N3884: C25.2 U1.5 | length 1084.5
  Inner3 w13: U1.5 3325.01,3505.01 3465,3645 3970,3645 v1(4080,3535)
  Bottom Layer w13: v1(4080,3535) 4105,3510 C25.2
$1I297\BYPASS: C18.2 U3.33 | length 269.1
  Top Layer w13: C18.2 4249.37,3270.63 v2(4250,3270) ; U3.33 4364.15,3440.85 4365.41,3439.59 4365.56,3439.59 4372.87,3432.28 4372.87,3432.13 v2(4385,3420)
  Bottom Layer w13: v2(4250,3270) 4265,3270 4385,3390 v2(4385,3420)
$1I297\CLKBUF: U3.21
$1I297\CPOUT: C20.2 U3.24 U9.2 | length 242.5
  Top Layer w13: v1(4249.37,3659.68) 4249.37,3628.74 U9.2 ; v2(4355,3655) 4374.13,3635.87 U3.24
  Bottom Layer w10: C20.2 4294.37,3655
  Bottom Layer w13: v1(4249.37,3659.68) 4254.05,3655 4294.37,3655 v2(4355,3655)
$1I297\CS#: U3.15
$1I297\D1: U3.23
$1I297\D2: U3.11
$1I297\D3: U3.8
$1I297\D4: U3.34
$1I297\D5: U3.14
$1I297\D6: U3.3
$1I297\D7: U3.6
$1I297\DIN: U3.19
$1I297\PLL_LOCK: U3.22
$1I297\RSSI: U3.16
$1I297\RXHP: U3.40 | length 44
  Top Layer w13: U3.40 4431.93,3353.6 4431.93,3373.22 4437.33,3378.62 v1(4437.33,3393.49)
$1I297\RXN: U3.5 U6.6 | length 234
  Top Layer w13: U3.5@4620.23,3460.55 4734.89,3460.55 4755.9,3439.53 4821.18,3439.53 4834.87,3425.84 U6.6
$1I297\RXP: U3.4 U6.4 | length 210.7
  Top Layer w13: U3.4 4648.98,3440.85 4649.33,3441.2 4727.37,3441.2 4734.8,3433.77 4734.8,3389.49 U6.4
$1I297\RXTX_MODE: U3.48 | length 52.4
  Top Layer w13: U3.48 4590.73,3334.27 v1(4615,3310)
$1I297\SCLK: U3.18
$1I297\SHDN#: U3.12 X1.1
$1I297\TUNE: C22.2 U3.32 U8.1 U9.1 | length 380.6
  Top Layer w13: U8.1 4174.37,3448.74 C22.2@4174.37,3530 ; U9.1 C22.2@4174.37,3530 ; U3.32 4314.45,3460.55 4290,3485 4219.37,3485 C22.2@4174.37,3530
$1I297\TXN: U3.10 U7.6 | length 245.3
  Top Layer w13: U3.10 4648.98,3559 4649.33,3558.65 4738.65,3558.65 4755,3575 4755,3631.7 U7.6@4788.17,3664.87
$1I297\TXP: U3.9 U7.4 | length 267.2
  Top Layer w13: U3.9 4658.98,3539.3 4659.33,3539.65 4749.65,3539.65 4770,3560 4834.72,3560 4858.88,3584.16 U7.4@4858.88,3594.16
$1I297\XTAL: C19.2 C24.2 C25.1 U3.28 | length 299.6
  Top Layer w13: U3.28 v2(4380,3539.3)
  Bottom Layer w10: C19.2 4300.07,3539.3 v2(4380,3539.3)
  Bottom Layer w13: C24.2 4249.37,3508.74 C25.1
+5V: X1.4
GND: C18.1 C20.1 C21.1 C22.1 C23.2 C26.1 C28.1 C30.2 C31.1 C32.1 C33.2 C35.2 C36.1 C37.1 C38.1 C39.1 C40.1 C41.1 CLNA1.2 CPA1.2 CPA2.2 CPA3.2 CPLL1.2 CRXMX1.2 CTXMX1.2 CVCCCP1.2 CVCO0.2 CVCO1.2 CVCO2.2 CVRXA1.2 CVRXF1.2 CVXTAL1.2 U1.1 U1.2 U1.3 U1.4 U2.5 U2.7 U2.12 U2.31 U2.32 U2.37 U2.42 U3.2 U3.26 U3.31 U3.47 U3.49 U4.1 U4.2 U4.3 U4.4 U5.1 U5.2 U5.3 U5.4 U6.1 U6.2 U7.1 U7.2 X1.2 | length 93.9
  Top Layer w13: v2@4309.8,3578.65 U3.26 ; U3.47 4571.04,3382.42 v1(4591.47,3402.86)
  other v1: 4484.75,3494.54 4497.74,3590 4542.74,3593.74 4412.74,3785.55 4234.45,3798.31
  other v2: 4309.8,3578.65
RXIN: U2.4 U3.37 | length 903.2
  Top Layer w13: v2(3743.72,3582.98) 3749.21,3588.48 U2.4 ; v1(4354.13,3309.9) 4354.13,3332.3 U3.37
  Inner3 w13: v2(3743.72,3582.98) 3749.22,3577.48 3749.22,3572.84 3751.78,3570.28 3751.78,3508.99 3777.82,3482.95 3924.18,3482.95 3952.13,3455 4287.77,3455 4325.62,3417.14 4325.62,3397.33 4354.13,3368.83 v1(4354.13,3309.9)
RXIP: U2.3 U3.38 | length 893.5
  Top Layer w13: U2.3 3768.9,3587.79 v2(3773.7,3582.98) ; v1@4393.83,3315.09 U3.38
  Inner3 w13: v2(3773.7,3582.98) 3770.78,3580.06 3770.78,3516.86 3785.12,3502.52 3931.48,3502.52 3959,3475 4294.64,3475 4344.62,3425.02 4344.62,3405.2 4381.09,3368.74 4381.09,3343.28 4389.05,3335.32 v1(4389.05,3310.31)
RXQN: U2.9 U3.35 | length 871.3
  Top Layer w13: U2.9 3650.79,3587.79 v2(3655.59,3582.98) ; v1(4301.13,3407) 4306.63,3401.5 U3.35
  Inner2 w13: v2(3655.59,3582.98) 3650.59,3577.98 3650.59,3574.87 3655.11,3570.35 3655.11,3524.48 3785.59,3394 3989.2,3394 3999.2,3404 4002.07,3404 4007.07,3409 ; 4010,3409 4007.07,3409 ; v2(4037.57,3414.49) 4012.57,3414.49 4007.07,3409
  Inner3 w13: v2(4037.57,3414.49) 4062.57,3414.49 4069.35,3407.71 4104.28,3407.71 4110.48,3401.5 4270.62,3401.5 4276.12,3407 v1(4301.13,3407)
RXQP: U2.10 U3.36 | length 897.2
  Top Layer w13: v2(3625.61,3582.98) 3631.1,3588.48 U2.10 ; v1(4301.13,3377) 4305.93,3381.8 U3.36
  Inner2 w13: v2(3625.61,3582.98) 3625.61,3572.98 3636.11,3562.48 3636.11,3516.61 3777.72,3375 3997.07,3375 4007.07,3385 4034.49,3385 v2(4037.57,3381.92)
  Inner3 w13: v2(4037.57,3381.92) 4062.57,3381.92 4069.35,3388.71 4096.41,3388.71 4102.61,3382.5 4270.62,3382.5 4276.12,3377 v1(4301.13,3377)
TXIN: U2.44 U3.44 | length 1095.3
  Top Layer w13: v2(3795.27,3527) 3802.74,3519.53 U2.44 ; v1(4506.78,3319.75) 4511.94,3324.9 U3.44
  Inner2 w13: v2(3795.27,3527) 3820.27,3527 3827.12,3533.85 3850.71,3533.85 3926.85,3610 4360.66,3610 4424.15,3546.51 4481.52,3546.51 4547.43,3480.6 4547.43,3360.4 v1(4506.78,3319.75)
TXIP: U2.45 U3.45 | length 1189.4
  Top Layer w13: v2(3797.98,3559.7) 3808.68,3549.01 3808.68,3548.22 3815.99,3540.9 3816.78,3540.9 3818.48,3539.21 U2.45 ; U3.45 4531.63,3290.39 v1(4532.24,3289.78)
  Inner2 w13: v2(3797.98,3559.7) 3822.98,3559.7 3829.84,3552.85 3842.84,3552.85 3914.98,3625 ; 3909.98,3625 3914.98,3625 ; 4367.53,3630 4368.53,3629 ; v1(4532.24,3289.78) 4549.92,3307.46 4549.92,3321.74 4566.98,3338.8 4566.98,3487.92 4489.39,3565.51 4432.02,3565.51 4368.53,3629 ; 3914.98,3625 3918.98,3629 4368.53,3629
TXQN: U2.40 U3.42 | length 856.3
  Top Layer w10: v2(3800.95,3428.48) 3813.25,3440.79 U2.40
  Top Layer w13: v1(4467.33,3388.54) 4472.58,3383.29 U3.42
  Inner2 w13: v2(3800.95,3428.48) 3825.95,3428.48 3831.44,3433.98 3849.38,3433.98 3917.7,3502.3 4015.83,3502.3 4061.71,3456.42 4449.95,3456.42 4473.58,3432.79 4473.58,3419.79 4467.33,3413.54 v1(4467.33,3388.54)
TXQP: U2.41 U3.43 | length 891
  Top Layer w10: v2(3797.94,3458.47) 3799.94,3460.47 U2.41
  Top Layer w13: U3.43 4492.29,3379.95 v2(4498.83,3386.49)
  Inner2 w13: v2(3797.94,3458.47) 3801.25,3455.16 3826.25,3455.16 3892.38,3521.3 4023.7,3521.3 4069.58,3475.42 4457.82,3475.42 4495.89,3437.35 4495.89,3414.43 4502.14,3408.18 4502.14,3389.8 v2(4498.83,3386.49)
VCC: C28.2 C30.1 C31.2 C32.2 C33.1 C36.2 C38.2 C39.2 C40.2 C41.2 U2.2 U2.8 U2.11 U2.18 U2.33 U2.39 U2.43 U2.46 | length 787.4
  Top Layer w10: U2.33 3752.4,3351.87 3752.4,3336.73 3810.43,3278.71 C40.2 ; U2.39 3865,3421.1 C33.1 ; U2.43 3850.09,3499.84 3893.32,3456.6 C28.2 3909.06,3455.03 v1(3909.06,3434.02) ; U2.46 C38.2@3889.46,3558.9
  Top Layer w13: C31.2 3611.42,3666.96 U2.11 ; C32.2 3670.47,3691.54 U2.8 ; C30.1 3788.58,3654.85 U2.2
  Bottom Layer w10: v1(3909.06,3434.02) 3909.06,3295.91 v1(3910.63,3294.34)
pads on no net: H1.1 H1.2 H1.3 H1.4 H1.5 H1.6 H1.7 H1.8 H1.9 H1.10 H1.11 H1.12 H1.13 H1.14 H1.15 H1.16 H1.17 H1.18 H1.19 H1.20 H2.1 H2.2 H2.3 H2.4 H2.5 H2.6 H2.7 H2.8 H2.9 H2.10 H2.11 H2.12 H2.13 H2.14 H2.15 H2.16 H2.17 H2.18 H2.19 H2.20 U2.17 U2.38 U2.49 U6.5 U7.5 U27.3 U27.9 U27.10 U27.11 U27.12 U27.13 U27.14 U27.15 U27.16 U27.17 U27.18 U27.19 U27.20 U27.21 U27.22 U27.23 U27.24 U27.25 U27.26 U27.27 U27.28 U27.30 U27.33 U27.35 U27.36 U27.37 U27.38

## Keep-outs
Board Outline Layer:
  the board outline again, w10

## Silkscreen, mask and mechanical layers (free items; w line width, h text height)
Top Silkscreen Layer:
  text "C38" at 4144.79,3597.83 h45 r180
